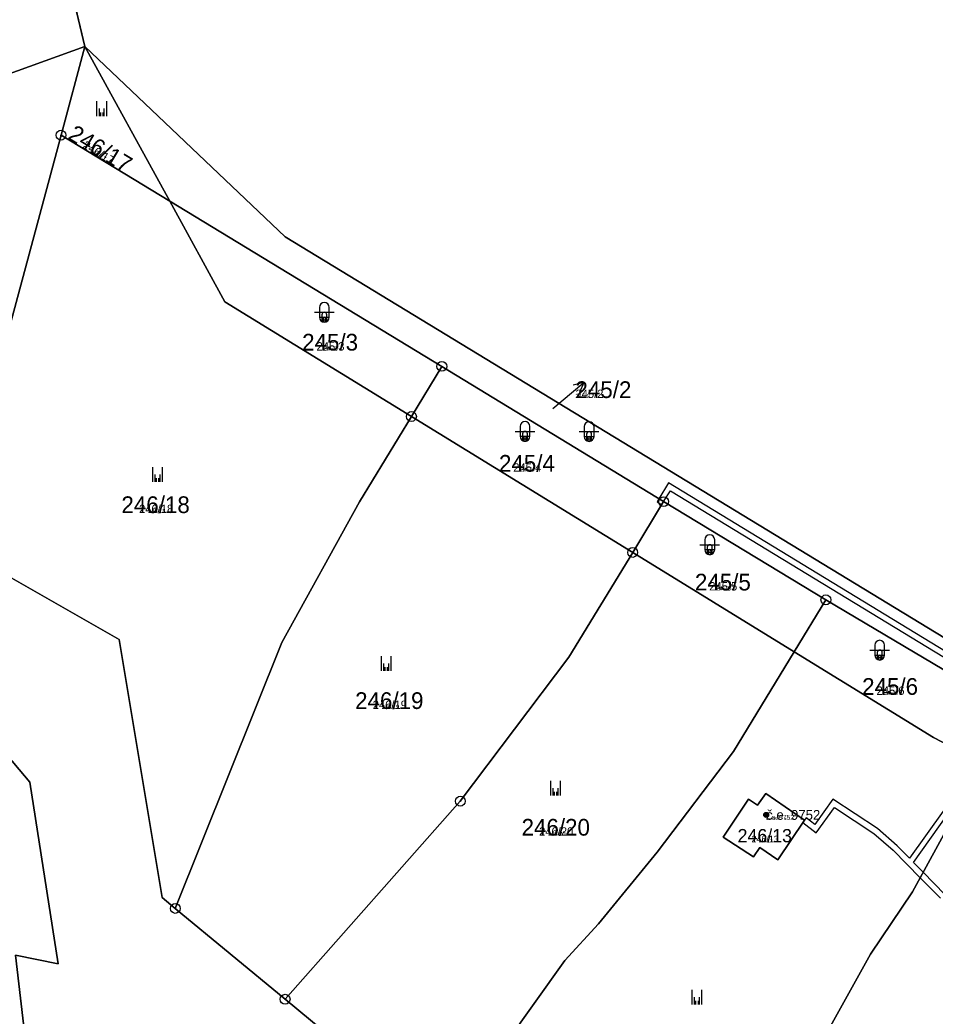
# Model space of a CAD drawing. Extents: x -759873 to -758487, y -975024 to -973516.
# Drawn here: x -759165.8 to -759072.7, y -974576.4 to -974475 of the extents above; entities that cross this region are included whole.
import ezdxf

# ---------------------------------------------------------------- set-up
doc = ezdxf.new("R2010")
doc.units = 0
for name, color, linetype in [('KAT_02_hranice parcel', 7, 'Continuous'), ('KAT_03_1000_st čísla parcelní', 7, 'Continuous'), ('KAT_03_1000_čísla parcelní', 7, 'Continuous'), ('KAT_03_1000_čísla popisná', 7, 'Continuous'), ('KAT_03_250_st čísla parcelní', 7, 'Continuous'), ('KAT_03_250_čísla parcelní', 7, 'Continuous'), ('KAT_03_250_čísla popisná', 7, 'Continuous'), ('KAT_03_500_st čísla parcelní', 7, 'Continuous'), ('KAT_03_500_čísla parcelní', 7, 'Continuous'), ('KAT_03_500_čísla popisná', 7, 'Continuous'), ('KAT_05_1000_značky kultur', 7, 'Continuous'), ('KAT_05_250_značky kultur', 7, 'Continuous'), ('KAT_05_500_značky kultur', 7, 'Continuous'), ('KAT_07_1000_značky budov', 7, 'Continuous'), ('KAT_07_250_značky budov', 7, 'Continuous'), ('KAT_07_500_značky budov', 7, 'Continuous'), ('KAT_10_věcná břemena', 7, 'Continuous'), ('KAT_11_značky bodu BP', 7, 'Continuous'), ('KAT_12_pomocná šipka', 7, 'Continuous'), ('KAT_14_plocha_budovy', 7, 'Continuous'), ('KAT_14_plocha_pozemek', 7, 'Continuous')]:
    doc.layers.add(name, color=color, linetype=linetype)

msp = doc.modelspace()

# ---------------------------------------------------------------- linework, layer by layer
at = {"layer": 'KAT_02_hranice parcel'}
for p, q in [((-759159.14, -974477.67), (-759164.42, -974455.5)), ((-759161.57, -974486.7), (-759159.14, -974477.67)), ((-759159.14, -974477.67), (-759150.51, -974493.42)), ((-759161.57, -974486.7), (-759150.51, -974493.42)), ((-759150.51, -974493.42), (-759122.84, -974510.23)), ((-759125.93, -974515.33), (-759122.84, -974510.23)), ((-759122.84, -974510.23), (-759100.28, -974524)), ((-759125.93, -974515.33), (-759103.43, -974529.17)), ((-759103.43, -974529.17), (-759100.28, -974524)), ((-759100.28, -974524), (-759083.78, -974533.99)), ((-759103.43, -974529.17), (-759087, -974539.27)), ((-759087, -974539.27), (-759083.78, -974533.99)), ((-759083.78, -974533.99), (-759064.86, -974545.21)), ((-759138.78, -974574.64), (-759149.95, -974565.4)), ((-759123.88, -974586.97), (-759138.78, -974574.64))]:
    msp.add_line(p, q, dxfattribs=at)
for points in [[(-759172.37, -974482.45), (-759171.66, -974482.19), (-759159.14, -974477.67)], [(-759159.14, -974477.67), (-759138.76, -974497.06), (-759068.5, -974539.82), (-759037.83, -974556.56)], [(-759124.04, -974618.94), (-759128.67, -974614.12), (-759132.72, -974605.42), (-759137.89, -974601.46), (-759140.41, -974591.83), (-759141.66, -974587.58), (-759147.81, -974582.84), (-759161.09, -974585.41), (-759165.12, -974579.47), (-759166.21, -974570.14), (-759161.85, -974571.03), (-759164.75, -974552.56), (-759173.97, -974541.64), (-759175.43, -974540.05), (-759178.37, -974531.68), (-759179.47, -974515.71), (-759177.07, -974506.79), (-759176.34, -974497.63), (-759172.37, -974482.45)], [(-759149.95, -974565.4), (-759151.3, -974564.28), (-759155.66, -974538.03), (-759168.27, -974530.82), (-759169.41, -974515.83), (-759161.57, -974486.7)], [(-759150.51, -974493.42), (-759144.9, -974503.66), (-759125.93, -974515.33)], [(-759149.95, -974565.4), (-759139.11, -974538.34), (-759131.21, -974524.03), (-759125.93, -974515.33)], [(-759138.78, -974574.64), (-759120.96, -974554.48), (-759109.92, -974539.83), (-759103.43, -974529.17)], [(-759122.47, -974587.73), (-759110.32, -974570.69), (-759106.9, -974566.95), (-759100.94, -974559.67), (-759093.17, -974549.44), (-759087, -974539.27)], [(-759087, -974539.27), (-759072.82, -974547.99), (-759067.83, -974550.62)], [(-759100.16, -974608.12), (-759088.78, -974587.22), (-759079.24, -974570.06), (-759074.96, -974563.7), (-759067.83, -974550.62)], [(-759090.75, -974554.88), (-759091.65, -974554.27), (-759094.21, -974558.13), (-759091.13, -974560.16), (-759090.49, -974559.21), (-759088.66, -974560.45), (-759085.95, -974556.41), (-759089.89, -974553.7), (-759090.75, -974554.88)]]:
    msp.add_lwpolyline(points, dxfattribs=at)
at = {"layer": 'KAT_03_1000_čísla popisná'}
msp.add_circle((-759089.85, -974555.88), 0.25, dxfattribs=at)
at = {"layer": 'KAT_03_250_čísla popisná'}
msp.add_circle((-759089.85, -974555.88), 0.0625, dxfattribs=at)
at = {"layer": 'KAT_03_500_čísla popisná'}
msp.add_circle((-759089.85, -974555.88), 0.125, dxfattribs=at)
at = {"layer": 'KAT_05_1000_značky kultur'}
for p, q in [((-759157.92, -974484.75), (-759157.92, -974483.25)), ((-759156.92, -974484.75), (-759156.92, -974483.25)), ((-759135.79, -974504.73), (-759133.79, -974504.73)), ((-759135.29, -974504.23), (-759135.29, -974505.23)), ((-759134.29, -974505.23), (-759134.29, -974504.23)), ((-759114.88, -974516.35), (-759114.88, -974517.35)), ((-759113.88, -974517.35), (-759113.88, -974516.35)), ((-759115.38, -974516.85), (-759113.38, -974516.85)), ((-759108.86, -974516.86), (-759106.86, -974516.86)), ((-759108.36, -974516.36), (-759108.36, -974517.36)), ((-759107.36, -974517.36), (-759107.36, -974516.36)), ((-759152.25, -974521.98), (-759152.25, -974520.48)), ((-759151.25, -974521.98), (-759151.25, -974520.48)), ((-759096.59, -974528.38), (-759094.59, -974528.38)), ((-759096.09, -974527.88), (-759096.09, -974528.88)), ((-759095.09, -974528.88), (-759095.09, -974527.88)), ((-759078.8, -974538.61), (-759078.8, -974539.61)), ((-759077.8, -974539.61), (-759077.8, -974538.61)), ((-759079.3, -974539.11), (-759077.3, -974539.11)), ((-759128.99, -974541.21), (-759128.99, -974539.71)), ((-759127.99, -974541.21), (-759127.99, -974539.71)), ((-759111.76, -974553.9), (-759111.76, -974552.4)), ((-759110.76, -974553.9), (-759110.76, -974552.4)), ((-759097.38, -974575.18), (-759097.38, -974573.68)), ((-759096.38, -974575.18), (-759096.38, -974573.68))]:
    msp.add_line(p, q, dxfattribs=at)
for centre, start, end in [((-759134.79, -974504.23), 0, 180), ((-759134.79, -974505.23), 180, 359.9879), ((-759114.38, -974516.35), 0, 180), ((-759107.86, -974516.36), 0, 180), ((-759114.38, -974517.35), 180, 359.9879), ((-759107.86, -974517.36), 180, 359.9879), ((-759095.59, -974527.88), 0, 180), ((-759095.59, -974528.88), 180, 359.9879), ((-759078.3, -974538.61), 0, 180), ((-759078.3, -974539.61), 180, 359.9879)]:
    msp.add_arc(centre, 0.5, start, end, dxfattribs=at)
at = {"layer": 'KAT_05_250_značky kultur'}
for p, q in [((-759157.54, -974484.75), (-759157.54, -974484.38)), ((-759157.29, -974484.75), (-759157.29, -974484.38)), ((-759135.04, -974505.48), (-759134.54, -974505.48)), ((-759134.92, -974505.36), (-759134.92, -974505.61)), ((-759134.66, -974505.61), (-759134.66, -974505.36)), ((-759114.63, -974517.6), (-759114.13, -974517.6)), ((-759114.51, -974517.48), (-759114.51, -974517.73)), ((-759114.25, -974517.73), (-759114.25, -974517.48)), ((-759108.11, -974517.61), (-759107.61, -974517.61)), ((-759107.99, -974517.49), (-759107.99, -974517.74)), ((-759107.73, -974517.74), (-759107.73, -974517.49)), ((-759151.87, -974521.98), (-759151.87, -974521.6)), ((-759151.62, -974521.98), (-759151.62, -974521.6)), ((-759095.84, -974529.13), (-759095.34, -974529.13)), ((-759095.72, -974529.01), (-759095.72, -974529.26)), ((-759095.46, -974529.26), (-759095.46, -974529.01)), ((-759078.55, -974539.86), (-759078.05, -974539.86)), ((-759078.43, -974539.74), (-759078.43, -974539.99)), ((-759078.17, -974539.99), (-759078.17, -974539.74)), ((-759128.61, -974541.21), (-759128.61, -974540.83)), ((-759128.36, -974541.21), (-759128.36, -974540.83)), ((-759111.38, -974553.9), (-759111.38, -974553.53)), ((-759111.13, -974553.9), (-759111.13, -974553.53)), ((-759097, -974575.18), (-759097, -974574.81)), ((-759096.75, -974575.18), (-759096.75, -974574.81))]:
    msp.add_line(p, q, dxfattribs=at)
for centre, start, end in [((-759134.79, -974505.36), 0, 180), ((-759134.79, -974505.61), 180, 359.9879), ((-759114.38, -974517.48), 0, 180), ((-759107.86, -974517.49), 0, 180), ((-759114.38, -974517.73), 180, 359.9879), ((-759107.86, -974517.74), 180, 359.9879), ((-759095.59, -974529.01), 0, 180), ((-759095.59, -974529.26), 180, 359.9879), ((-759078.3, -974539.74), 0, 180), ((-759078.3, -974539.99), 180, 359.9879)]:
    msp.add_arc(centre, 0.125, start, end, dxfattribs=at)
at = {"layer": 'KAT_05_500_značky kultur'}
for p, q in [((-759157.67, -974484.75), (-759157.67, -974484)), ((-759157.17, -974484.75), (-759157.17, -974484)), ((-759135.04, -974504.98), (-759135.04, -974505.48)), ((-759134.54, -974505.48), (-759134.54, -974504.98)), ((-759135.29, -974505.23), (-759134.29, -974505.23)), ((-759114.88, -974517.35), (-759113.88, -974517.35)), ((-759114.63, -974517.1), (-759114.63, -974517.6)), ((-759114.13, -974517.6), (-759114.13, -974517.1)), ((-759108.36, -974517.36), (-759107.36, -974517.36)), ((-759108.11, -974517.11), (-759108.11, -974517.61)), ((-759107.61, -974517.61), (-759107.61, -974517.11)), ((-759152, -974521.98), (-759152, -974521.23)), ((-759151.49, -974521.98), (-759151.49, -974521.23)), ((-759096.09, -974528.88), (-759095.09, -974528.88)), ((-759095.84, -974528.63), (-759095.84, -974529.13)), ((-759095.34, -974529.13), (-759095.34, -974528.63)), ((-759078.8, -974539.61), (-759077.8, -974539.61)), ((-759078.55, -974539.36), (-759078.55, -974539.86)), ((-759078.05, -974539.86), (-759078.05, -974539.36)), ((-759128.74, -974541.21), (-759128.74, -974540.46)), ((-759128.23, -974541.21), (-759128.23, -974540.46)), ((-759111.51, -974553.9), (-759111.51, -974553.15)), ((-759111.01, -974553.9), (-759111.01, -974553.15)), ((-759097.13, -974575.18), (-759097.13, -974574.43)), ((-759096.62, -974575.18), (-759096.62, -974574.43))]:
    msp.add_line(p, q, dxfattribs=at)
for centre, start, end in [((-759134.79, -974504.98), 0, 180), ((-759134.79, -974505.48), 180, 359.9879), ((-759114.38, -974517.1), 0, 180), ((-759107.86, -974517.11), 0, 180), ((-759114.38, -974517.6), 180, 359.9879), ((-759107.86, -974517.61), 180, 359.9879), ((-759095.59, -974528.63), 0, 180), ((-759095.59, -974529.13), 180, 359.9879), ((-759078.3, -974539.36), 0, 180), ((-759078.3, -974539.86), 180, 359.9879)]:
    msp.add_arc(centre, 0.25, start, end, dxfattribs=at)
at = {"layer": 'KAT_07_1000_značky budov'}
msp.add_circle((-759089.86, -974555.88), 0.175, dxfattribs=at)
at = {"layer": 'KAT_07_250_značky budov'}
msp.add_circle((-759089.85, -974555.88), 0.0437, dxfattribs=at)
at = {"layer": 'KAT_07_500_značky budov'}
msp.add_circle((-759089.85, -974555.88), 0.0875, dxfattribs=at)
at = {"layer": 'KAT_10_věcná břemena'}
for points in [[(-759064.75, -974543.41), (-759099.77, -974522.09), (-759100.76, -974523.71), (-759100.95, -974524.02), (-759100.47, -974524.31), (-759100.28, -974524), (-759099.57, -974522.91), (-759065.31, -974543.77)], [(-759071.86, -974555.5), (-759075.29, -974560.28), (-759076.52, -974559.03), (-759078.53, -974557.28), (-759083.07, -974554.29), (-759084.89, -974556.86), (-759085.77, -974556.17), (-759085.95, -974556.41), (-759086.12, -974556.66), (-759084.77, -974557.72), (-759082.91, -974555.11), (-759078.89, -974557.76), (-759076.94, -974559.47), (-759074.18, -974562.27), (-759072.11, -974564.37)], [(-759071.67, -974563.97), (-759073.88, -974561.72), (-759074.87, -974560.71), (-759071.36, -974555.82)]]:
    msp.add_lwpolyline(points, dxfattribs=at)
at = {"layer": 'KAT_11_značky bodu BP'}
for centre, radius in [((-759161.57, -974486.7), 0.5), ((-759161.57, -974486.7), 0.0303), ((-759122.84, -974510.23), 0.5), ((-759122.84, -974510.23), 0.0303), ((-759125.93, -974515.33), 0.5), ((-759125.93, -974515.33), 0.0303), ((-759100.28, -974524), 0.5), ((-759100.28, -974524), 0.0303), ((-759103.43, -974529.17), 0.5), ((-759103.43, -974529.17), 0.0303), ((-759083.78, -974533.99), 0.5), ((-759083.78, -974533.99), 0.0303), ((-759120.96, -974554.48), 0.5), ((-759120.96, -974554.48), 0.0303), ((-759149.95, -974565.4), 0.5), ((-759149.95, -974565.4), 0.0303), ((-759138.78, -974574.64), 0.5), ((-759138.78, -974574.64), 0.0303)]:
    msp.add_circle(centre, radius, dxfattribs=at)
at = {"layer": 'KAT_12_pomocná šipka'}
for p, q in [((-759110.69, -974513.8), (-759108.39, -974511.87)), ((-759108.39, -974511.87), (-759109.48, -974512.13)), ((-759108.39, -974511.87), (-759108.84, -974512.9)), ((-759111.54, -974514.52), (-759110.69, -974513.8))]:
    msp.add_line(p, q, dxfattribs=at)
at = {"layer": 'KAT_14_plocha_budovy'}
msp.add_lwpolyline([(-759094.21, -974558.13), (-759091.13, -974560.16), (-759090.49, -974559.21), (-759088.66, -974560.45), (-759085.95, -974556.41), (-759089.89, -974553.7), (-759090.75, -974554.88), (-759091.65, -974554.27)], close=True, dxfattribs=at)
at = {"layer": 'KAT_14_plocha_pozemek'}
for points in [[(-759175.27, -974446.88), (-759172.37, -974482.45), (-759171.66, -974482.19), (-759159.14, -974477.67), (-759164.42, -974455.5), (-759165.63, -974450.4), (-759168.64, -974433.81), (-759181.64, -974397.69), (-759189.03, -974384.96), (-759194.73, -974407.56), (-759206.79, -974400.97), (-759217.05, -974393.25), (-759219.59, -974401.14), (-759220.81, -974404.94), (-759225.77, -974404.63), (-759227.77, -974404.51), (-759229.03, -974406.06), (-759225.39, -974407.7), (-759207.13, -974415.97), (-759198.3, -974417.97), (-759197.39, -974426.02), (-759191.99, -974436.47)], [(-759150.51, -974493.42), (-759159.14, -974477.67), (-759161.57, -974486.7)], [(-759100.28, -974524), (-759083.78, -974533.99), (-759064.86, -974545.21), (-759039.21, -974559.23), (-759037.83, -974556.56), (-759068.5, -974539.82), (-759138.76, -974497.06), (-759159.14, -974477.67), (-759150.51, -974493.42), (-759122.84, -974510.23)], [(-759131.21, -974524.03), (-759125.93, -974515.33), (-759144.9, -974503.66), (-759150.51, -974493.42), (-759161.57, -974486.7), (-759169.41, -974515.83), (-759168.27, -974530.82), (-759155.66, -974538.03), (-759151.3, -974564.28), (-759149.95, -974565.4), (-759139.11, -974538.34)], [(-759150.51, -974493.42), (-759144.9, -974503.66), (-759125.93, -974515.33), (-759122.84, -974510.23)], [(-759100.28, -974524), (-759122.84, -974510.23), (-759125.93, -974515.33), (-759103.43, -974529.17)], [(-759109.92, -974539.83), (-759103.43, -974529.17), (-759125.93, -974515.33), (-759131.21, -974524.03), (-759139.11, -974538.34), (-759149.95, -974565.4), (-759138.78, -974574.64), (-759120.96, -974554.48)], [(-759103.43, -974529.17), (-759087, -974539.27), (-759083.78, -974533.99), (-759100.28, -974524)], [(-759100.94, -974559.67), (-759093.17, -974549.44), (-759087, -974539.27), (-759103.43, -974529.17), (-759109.92, -974539.83), (-759120.96, -974554.48), (-759138.78, -974574.64), (-759123.88, -974586.97), (-759122.47, -974587.73), (-759110.32, -974570.69), (-759106.9, -974566.95)], [(-759087, -974539.27), (-759072.82, -974547.99), (-759067.83, -974550.62), (-759064.86, -974545.21), (-759083.78, -974533.99)], [(-759067.83, -974550.62), (-759072.82, -974547.99), (-759087, -974539.27), (-759093.17, -974549.44), (-759100.94, -974559.67), (-759106.9, -974566.95), (-759110.32, -974570.69), (-759122.47, -974587.73), (-759119.12, -974590.77), (-759122.45, -974602.82), (-759100.16, -974608.12), (-759088.78, -974587.22), (-759079.24, -974570.06), (-759074.96, -974563.7)], [(-759053.94, -974586.07), (-759041.97, -974564.24), (-759067.83, -974550.62), (-759074.96, -974563.7), (-759079.24, -974570.06), (-759088.78, -974587.22), (-759100.16, -974608.12), (-759088.47, -974610.92), (-759079.63, -974613.7), (-759068.68, -974616.85), (-759056.36, -974598.66), (-759059.73, -974595.66)], [(-759090.75, -974554.88), (-759091.65, -974554.27), (-759094.21, -974558.13), (-759091.13, -974560.16), (-759090.49, -974559.21), (-759088.66, -974560.45), (-759085.95, -974556.41), (-759089.89, -974553.7)], [(-759090.75, -974554.88), (-759089.89, -974553.7), (-759085.95, -974556.41), (-759088.66, -974560.45), (-759090.49, -974559.21), (-759091.13, -974560.16), (-759094.21, -974558.13), (-759091.65, -974554.27)]]:
    msp.add_lwpolyline(points, close=True, dxfattribs=at)
for points in [[(-759164.42, -974455.5), (-759159.14, -974477.67), (-759138.76, -974497.06), (-759068.5, -974539.82), (-759037.83, -974556.56), (-759016.55, -974568.17), (-758996.05, -974575.76)], [(-759169.41, -974515.83), (-759161.57, -974486.7), (-759159.14, -974477.67), (-759171.66, -974482.19)], [(-758985.91, -974649.95), (-759011.32, -974639.13), (-759058.27, -974633.29), (-759072.53, -974622.47), (-759085.12, -974612.91), (-759119.49, -974608.48), (-759126.45, -974601.07), (-759123.88, -974586.97), (-759138.78, -974574.64), (-759149.95, -974565.4), (-759151.3, -974564.28), (-759155.66, -974538.03), (-759168.27, -974530.82)], [(-759174.05, -974595), (-759148.58, -974619.46), (-759130.54, -974614.24), (-759126.29, -974619.41), (-759124.04, -974618.94), (-759128.67, -974614.12), (-759132.72, -974605.42), (-759137.89, -974601.46), (-759140.41, -974591.83), (-759141.66, -974587.58), (-759147.81, -974582.84), (-759161.09, -974585.41), (-759165.12, -974579.47), (-759166.21, -974570.14), (-759161.85, -974571.03), (-759164.75, -974552.56), (-759173.97, -974541.64)], [(-759173.97, -974541.64), (-759164.75, -974552.56), (-759161.85, -974571.03), (-759166.21, -974570.14), (-759165.12, -974579.47), (-759161.09, -974585.41), (-759147.81, -974582.84), (-759141.66, -974587.58), (-759140.41, -974591.83), (-759137.89, -974601.46), (-759132.72, -974605.42), (-759128.67, -974614.12), (-759124.04, -974618.94), (-759119.5, -974620.56), (-759109.03, -974624.43), (-759100.6, -974632.63), (-759078.61, -974645.91)]]:
    msp.add_lwpolyline(points, dxfattribs=at)

# ---------------------------------------------------------------- texts
at = {"layer": 'KAT_03_1000_st čísla parcelní'}
msp.add_text('246/13', height=1.353, dxfattribs=at).set_placement((-759092.76, -974558.67))
at = {"layer": 'KAT_03_1000_čísla parcelní'}
msp.add_text('246/17', height=1.7, rotation=329, dxfattribs=at).set_placement((-759160.98, -974487.02))
for s, p in [('245/3', (-759137.05, -974508.62)), ('245/2', (-759109.25, -974513.45)), ('245/4', (-759117.03, -974520.95)), ('246/18', (-759155.43, -974525.16)), ('245/5', (-759097.1, -974533.04)), ('245/6', (-759080.09, -974543.66)), ('246/19', (-759131.66, -974545.1)), ('246/20', (-759114.73, -974557.99))]:
    msp.add_text(s, height=1.7, dxfattribs=at).set_placement(p)
at = {"layer": 'KAT_03_1000_čísla popisná'}
msp.add_text('č.e. 9752', height=1, dxfattribs=at).set_placement((-759089.85, -974556.38))
at = {"layer": 'KAT_03_250_st čísla parcelní'}
msp.add_text('246/13', height=0.338, dxfattribs=at).set_placement((-759090.62, -974558.67))
at = {"layer": 'KAT_03_250_čísla parcelní'}
msp.add_text('246/17', height=0.425, rotation=329, dxfattribs=at).set_placement((-759158.68, -974488.4))
for s, p in [('245/3', (-759134.87, -974508.62)), ('245/2', (-759109.25, -974513.45)), ('245/4', (-759114.85, -974520.95)), ('246/18', (-759152.74, -974525.16)), ('245/5', (-759094.91, -974533.04)), ('245/6', (-759077.91, -974543.66)), ('246/19', (-759128.97, -974545.1)), ('246/20', (-759112.05, -974557.99))]:
    msp.add_text(s, height=0.425, dxfattribs=at).set_placement(p)
at = {"layer": 'KAT_03_250_čísla popisná'}
msp.add_text('č.e. 9752', height=0.25, dxfattribs=at).set_placement((-759089.85, -974556.38))
at = {"layer": 'KAT_03_500_st čísla parcelní'}
msp.add_text('246/13', height=0.676, dxfattribs=at).set_placement((-759091.34, -974558.67))
at = {"layer": 'KAT_03_500_čísla parcelní'}
msp.add_text('246/17', height=0.85, rotation=329, dxfattribs=at).set_placement((-759159.45, -974487.94))
for s, p in [('245/3', (-759135.59, -974508.62)), ('245/2', (-759109.25, -974513.45)), ('245/4', (-759115.58, -974520.95)), ('246/18', (-759153.64, -974525.16)), ('245/5', (-759095.64, -974533.04)), ('245/6', (-759078.63, -974543.66)), ('246/19', (-759129.87, -974545.1)), ('246/20', (-759112.95, -974557.99))]:
    msp.add_text(s, height=0.85, dxfattribs=at).set_placement(p)
at = {"layer": 'KAT_03_500_čísla popisná'}
msp.add_text('č.e. 9752', height=0.5, dxfattribs=at).set_placement((-759089.85, -974556.38))

doc.saveas('drawing.dxf')
